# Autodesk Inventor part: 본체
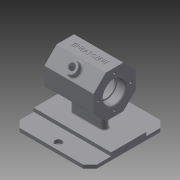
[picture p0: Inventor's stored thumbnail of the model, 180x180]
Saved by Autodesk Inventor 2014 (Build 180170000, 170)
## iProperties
Created: 2018-06
Part Number: 본체
Material: Generic
Document SubType Name: Modeling
Designer: kh
Density: 1 g/cm^3
Appearance: Default
Mass: 204.345 g
Surface Area: 602.491 cm^2
Volume: 204.345 cm^3
Author: kh
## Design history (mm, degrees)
sketch "Sketch1"
  geometry: L1 (-55, -55)-(55, -55); L2 (55, -55)-(55, 55); L3 (55, 55)-(-55, 55); L4 (-55, 55)-(-55, -55); L5 (-55, -55)-(55, 55); L6 (55, -55)-(-55, 55); 1 further point
  constraints: 12 end point, 2 midpoint, 2 parallel, 1 horizontal, 1 perpendicular
  dimensions: "d0" = 110 distance of L3.end L2.end; "d1" = 110 distance of L3.end L1.start
extrude "Extrusion1" new body sketch "Sketch1" distance "d2" = 5; taper "d3" = 0 deg
chamfer "Chamfer1" distance "d4" = 10; stored, may be unused: second distance "d5" = 2, angle "d6" = 45 deg
sketch "Sketch2"
  geometry: L1 (-45, -55)-(-55, -45) reference; L2 (-45, -55)-(45, -55) reference; L3 (55, -45)-(45, -55) reference; L4 (55, -45)-(55, 45) reference; L5 (45, 55)-(55, 45) reference; L6 (45, 55)-(-45, 55) reference; L7 (-55, 45)-(-45, 55) reference; L8 (-55, 45)-(-55, -45) reference; L9 (-55, 25)-(55, 25); L10 (55, 25)-(55, -25); L11 (55, -25)-(-55, -25); L12 (-55, -25)-(-55, 25); L13 (0, 0)-(0, 55)
  constraints: 10 end point, 2 parallel, 2 point on line, 1 horizontal, 1 midpoint, 1 perpendicular
  dimensions: "d7" = 30 distance between parallel lines of L11 L2; "d8" = 30 distance between parallel lines of L9 L6
extrude "Extrusion2" join sketch "Sketch2" distance "d9" = 5; taper "d10" = 0 deg
workplane "Work Plane1"
sketch "Sketch3"
  geometry: L1 (35, 62)-(-35, 62); L2 (-35, 92)-(35, 92); L3 (-35, 92)-(-35, 62); L4 (35, 92)-(35, 62); 1 further point
  constraints: 8 end point, 2 parallel, 1 perpendicular
  dimensions: "d13" = 70 distance of L2.start L2.end
revolve "Revolution1" sketch "Sketch3" stored, may be unused: angle "d15" = 90 deg
sketch "Sketch4"
  geometry: L1 (-55, -45)-(-45, -55) reference; L2 (-55, 45)-(-55, -45) reference; L3 (-45, 55)-(-55, 45) reference; L4 (45, 55)-(-45, 55) reference; L5 (55, 45)-(45, 55) reference; L6 (55, -45)-(55, 45) reference; L7 (45, -55)-(55, -45) reference; L8 (-45, -55)-(45, -55) reference; L9 (55, -25)-(-55, -25) reference; L10 (-19, 0)-(19, 0); L11 (-19, -5)-(19, -5); L12 (19, 5)-(-19, 5); A1 r 5 centre (-19, 0) between (-19, 5) and (-19, -5); A2 r 5 centre (19, 0) between (19, -5) and (19, 5); 2 further points
  constraints: 8 end point, 4 point on circle, 4 tangent, 2 centre point, 2 parallel, 1 coincident, 1 midpoint
  dimensions: "d16" = 38 distance of L10.start L10.end; "d17" = 10 diameter of A2
extrude "Extrusion3" join sketch "Sketch4" stored distance "d18" = 5; taper "d19" = 0 deg
sketch "Sketch5"
  geometry: L1 (35, -30)-(35, 30) reference; L2 (55, -45)-(55, -25) reference; L3 (-45, -55)-(45, -55) reference; L4 (0, -55)-(0, -25); L5 (-13.688, -45)-(25.666, -45); 2 further points
  constraints: 4 end point, 2 perpendicular, 2 point on line, 1 midpoint
  dimensions: "d20" = 10 distance between parallel lines of L5 L3
hole "Hole1" sketch "Sketch5" at (0, -45) diameter "d21" = 10; stored, may be unused: countersink angle "d25" = 90 deg, drill point angle "d27" = 118 deg; dims "d22" = 6, "d23" = 4, "d24" = 2, "d26" = 8
mirror "Mirror1"
sketch "Sketch6"
  geometry: L1 (30, -12.426)-(12.426, -30); L2 (12.426, -30)-(-12.426, -30); L3 (-12.426, -30)-(-30, -12.426); L4 (-30, -12.426)-(-30, 12.426); L5 (-30, 12.426)-(-12.426, 30); L6 (-12.426, 30)-(12.426, 30); L7 (12.426, 30)-(30, 12.426); L8 (30, 12.426)-(30, -12.426); L9 (0, 0)-(30, 0); 2 further points
  constraints: 18 end point, 1 coincident, 1 horizontal alignment, 1 midpoint, 1 perpendicular, 18 other
extrude "Extrusion4" join sketch "Sketch6" distance "d28" = 70; taper "d29" = 0 deg
sketch "Sketch7"
  geometry: L1 (-35, 49.574)-(-35, 74.426) reference; L2 (35, 49.574)-(35, 74.426) reference; L3 (-35, 62)-(35, 62); L4 (-23, 78)-(-23, 76); L5 (-23, 76)-(-19.455, 76); L6 (-19.455, 76)-(-19.455, 87); L7 (-19.455, 87)-(20.545, 87); L8 (20.545, 87)-(20.545, 76); L9 (20.545, 76)-(23, 76); L10 (-23, 78)-(-35, 78); L11 (23, 76)-(23, 78); L12 (23, 78)-(35, 78); L13 (-35, 78)-(-35, 62); L14 (35, 78)-(35, 62); 1 further point
  constraints: 24 end point, 3 perpendicular, 2 collinear, 2 midpoint, 2 parallel, 1 point on line
  dimensions: "d30" = 32 diameter of L10 L3; "d31" = 28 diameter of L5 L3; "d32" = 50 diameter of L7 L3; "d33" = 28 diameter of L9 L3; "d34" = 32 diameter of L12 L3; "d35" = 12 distance between parallel lines of L4 L13; "d37" = 12 distance of L11.end L12.end; "d38" = 40 distance between parallel lines of L8 L6
revolve "Revolution2" sketch "Sketch7" stored, may be unused: angle "d39" = 90 deg
sketch "Sketch8" dims "d40" = 46
  geometry: L1 (42.426, 42.426)-(60, 24.853) reference; L2 (17.574, 42.426)-(42.426, 42.426) reference; L3 (0, 24.853)-(17.574, 42.426) reference; L4 (0, 0)-(0, 24.853) reference; L5 (17.574, -17.574)-(0, 0) reference; L6 (42.426, -17.574)-(17.574, -17.574) reference; L7 (60, 0)-(42.426, -17.574) reference; L8 (60, 24.853)-(60, 0) reference; L9 (30, 12.426)-(60, 12.426); C1 r 14 at (30, 12.426) reference; C2 r 16 at (30, 12.426) reference; 3 further points
  constraints: 2 end point, 1 coincident, 1 horizontal alignment, 1 midpoint, 2 other
hole "Hole2" sketch "Sketch8" at (53, 12.426) diameter "d41" = 3.459; stored, may be unused: countersink angle "d45" = 90 deg, drill point angle "d47" = 118 deg; dims "d42" = 8, "d43" = 4, "d44" = 2, "d46" = 10
pattern_circular "Circular Pattern1" dims angle "d49" = 360 deg
mirror "Mirror2"
sketch "Sketch9"
  geometry: L1 (10.113, 16.029)-(59.887, 16.029); L2 (59.887, 16.029)-(59.887, 8.824); L3 (59.887, 8.824)-(10.113, 8.824); L4 (10.113, 8.824)-(10.113, 16.029); L5 (10.113, 16.029)-(59.887, 8.824); L6 (10.113, 8.824)-(59.887, 16.029); 2 further points
  constraints: 4 end point, 1 coincident, 1 midpoint, 2 other
emboss "Emboss1" sketch "Sketch9" dims "d0" = 110, "d1" = 110, "d51" = 0.5, "d52" = 0
workplane "Work Plane2"
sketch "Sketch10"
  geometry: L1 (70, 0)-(70, -24.853) reference; L2 (0, 0)-(70, 0) reference; L3 (0, 0)-(0, -24.853) reference; L4 (0, -24.853)-(70, -24.853) reference; L5 (35, -4.656)-(35, -24.853); L6 (0, -12.426)-(58.315, -12.426); C1 r 8 at (35, -12.426); 2 further points
  constraints: 4 end point, 2 midpoint, 2 perpendicular, 2 point on line, 1 centre point, 1 coincident
  dimensions: "d54" = 35 distance between parallel lines of L5 L3; "d55" = 16 diameter of C1
extrude "Extrusion5" join sketch "Sketch10" stored distance "d56" = 0; taper "d57" = 0 deg
sketch "Sketch11"
  geometry: C1 r 8 at (0, 0) reference; C2 r 4 at (0, 0); 1 further point
  constraints: 1 centre point, 1 coincident
  dimensions: "d58" = 8 diameter of C2
extrude "Extrusion6" cut sketch "Sketch11" stored distance "d59" = 70; taper "d60" = 0 deg
fillet "Fillet1" dims "d61" = 3
fillet "Fillet2" dims "d62" = 2
fillet "Fillet3" dims "d63" = 1
chamfer "Chamfer2" distance "d64" = 1; stored, may be unused: second distance "d65" = 2, angle "d66" = 45 deg
chamfer "Chamfer3" distance "d67" = 1; stored, may be unused: second distance "d68" = 2, angle "d69" = 45 deg
fillet "Fillet4" dims "d70" = 3, "d71" = 0.3
body "Solid1"
node "Projected Loop1"
node "Projected Loop2"
node "Projected Loop3"
node "Projected Loop4"
node "Projected Loop5"
node "Projected Loop6"
other parameters: "d11" = 0, "d53" = 7
